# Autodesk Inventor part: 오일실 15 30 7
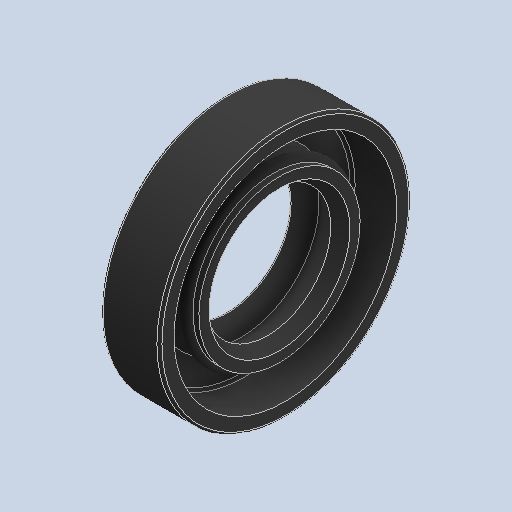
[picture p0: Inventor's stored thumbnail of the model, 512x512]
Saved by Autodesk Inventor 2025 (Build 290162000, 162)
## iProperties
Created: 2024-07
Part Number: 오일실 15 30 7
Material: 고무
Description: 오일-실
Document SubType Name: Modeling
Designer: anfro
Density: 0.93 g/cm^3
Appearance: 기본값
Author: jhkim
Sending System: Autodesk Inventor 2025
Preprocessor: ST-DEVELOPER v20
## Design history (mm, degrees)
feature "Solid1"
node "솔리드1"
